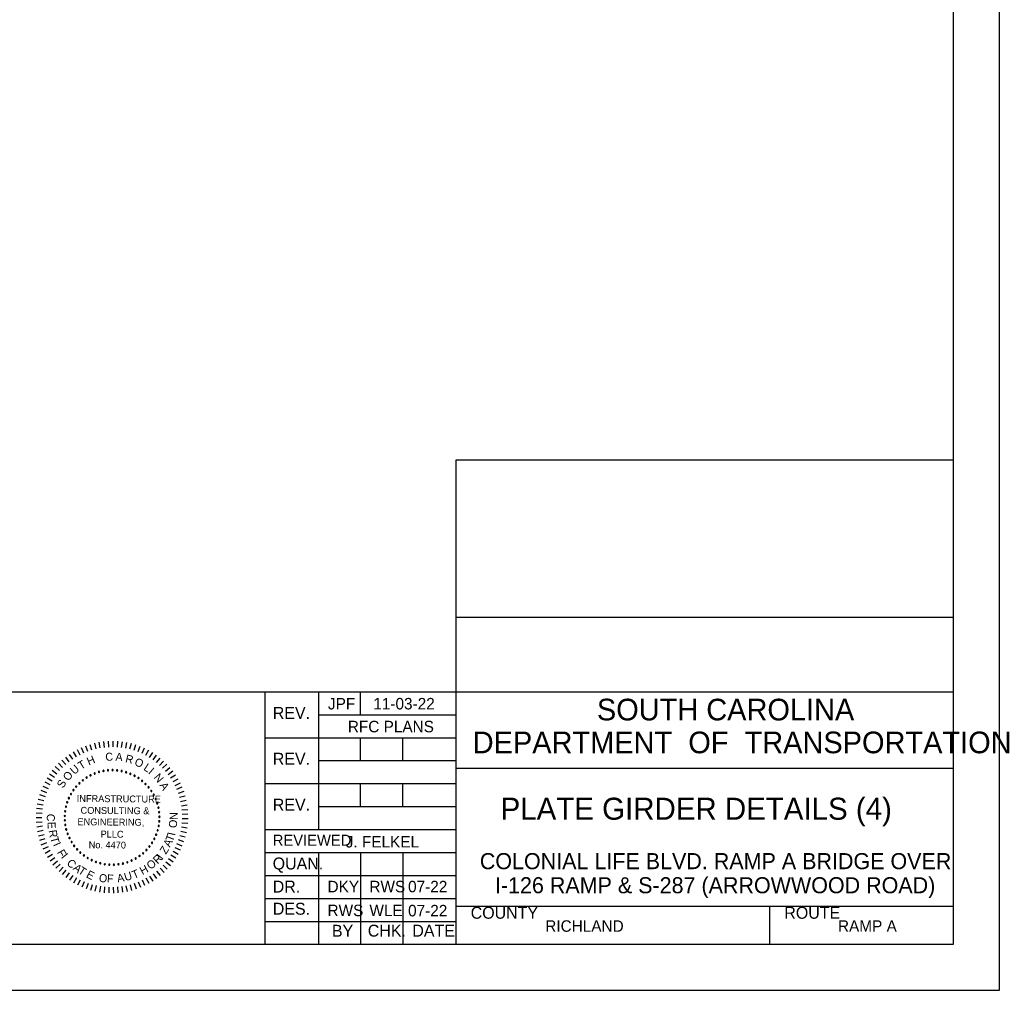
# Model space of a CAD drawing. Extents: x -383 to 11, y -361 to -94.
# Drawn here: x -203.87 to -160.75, y -187.49 to -145.21 of the extents above; entities that cross this region are included whole.
import ezdxf

# ---------------------------------------------------------------- set-up
doc = ezdxf.new("R2010")
doc.units = 0
for name, color, linetype in [('BR_BORDER LINES', 7, 'Continuous'), ('BR_TEXT', 7, 'Continuous'), ('Level 31', 7, 'Continuous')]:
    doc.layers.add(name, color=color, linetype=linetype)

msp = doc.modelspace()

# ---------------------------------------------------------------- linework, layer by layer
at = {"layer": 'BR_BORDER LINES'}
for p, q in [((-163.178, -185.489), (-163.178, -101.489)), ((-184.846, -185.489), (-184.846, -164.383)), ((-184.846, -164.383), (-163.178, -164.383)), ((-184.845, -171.242), (-163.178, -171.242)), ((-214.64, -174.489), (-193.18, -174.489)), ((-193.18, -185.489), (-193.18, -174.489)), ((-193.18, -174.489), (-163.178, -174.489)), ((-190.846, -174.489), (-190.846, -180.489)), ((-189.013, -175.489), (-189.013, -174.489)), ((-190.846, -175.489), (-184.846, -175.489)), ((-193.18, -176.489), (-184.846, -176.489)), ((-189.013, -177.489), (-189.013, -176.489)), ((-187.179, -177.489), (-187.179, -176.489)), ((-190.846, -177.489), (-184.846, -177.489)), ((-184.846, -177.822), (-184.846, -177.822)), ((-184.846, -177.823), (-163.178, -177.823)), ((-193.18, -178.489), (-184.846, -178.489)), ((-189.013, -179.489), (-189.013, -178.489)), ((-187.179, -179.489), (-187.179, -178.489)), ((-190.846, -179.489), (-184.846, -179.489)), ((-193.18, -180.489), (-184.846, -180.489)), ((-193.18, -181.489), (-184.846, -181.489)), ((-190.846, -181.489), (-190.846, -185.489)), ((-189.013, -181.489), (-189.013, -185.489)), ((-187.179, -181.489), (-187.179, -185.489)), ((-193.18, -182.489), (-184.846, -182.489)), ((-193.18, -183.489), (-184.846, -183.489)), ((-184.846, -183.823), (-163.178, -183.823)), ((-184.456, -183.823), (-163.178, -183.823)), ((-171.179, -185.489), (-171.179, -183.823)), ((-193.18, -184.489), (-184.846, -184.489)), ((-297.843, -185.489), (-163.178, -185.489))]:
    msp.add_line(p, q, dxfattribs=at)
at = {"layer": 'BR_TEXT'}
for p, q in [((-200.615, -176.726), (-200.555, -176.974)), ((-200.417, -176.685), (-200.373, -176.936)), ((-200.217, -176.656), (-200.188, -176.909)), ((-200.016, -176.64), (-200.002, -176.894)), ((-199.814, -176.636), (-199.816, -176.89)), ((-199.612, -176.644), (-199.63, -176.898)), ((-199.411, -176.664), (-199.444, -176.917)), ((-199.212, -176.697), (-199.26, -176.947)), ((-199.015, -176.741), (-199.079, -176.988)), ((-201.546, -177.106), (-201.415, -177.324)), ((-201.37, -177.007), (-201.252, -177.233)), ((-201.188, -176.92), (-201.084, -177.153)), ((-201.001, -176.844), (-200.912, -177.082)), ((-200.81, -176.779), (-200.735, -177.023)), ((-198.821, -176.798), (-198.9, -177.04)), ((-198.631, -176.866), (-198.724, -177.103)), ((-198.446, -176.946), (-198.553, -177.177)), ((-198.265, -177.037), (-198.387, -177.261)), ((-198.091, -177.139), (-198.226, -177.355)), ((-202.182, -177.601), (-202.002, -177.781)), ((-202.035, -177.463), (-201.866, -177.654)), ((-201.879, -177.334), (-201.723, -177.535)), ((-201.716, -177.215), (-201.572, -177.425)), ((-197.923, -177.251), (-198.071, -177.458)), ((-197.762, -177.373), (-197.922, -177.571)), ((-197.609, -177.505), (-197.781, -177.693)), ((-202.57, -178.065), (-202.36, -178.21)), ((-202.45, -177.903), (-202.25, -178.06)), ((-202.321, -177.748), (-202.13, -177.917)), ((-197.464, -177.646), (-197.647, -177.823)), ((-197.329, -177.795), (-197.522, -177.961)), ((-197.202, -177.952), (-197.405, -178.106)), ((-202.779, -178.411), (-202.553, -178.529)), ((-202.679, -178.235), (-202.461, -178.366)), ((-197.086, -178.117), (-197.298, -178.258)), ((-196.979, -178.289), (-197.199, -178.417)), ((-196.883, -178.467), (-197.111, -178.581)), ((-202.944, -178.779), (-202.705, -178.869)), ((-202.867, -178.593), (-202.634, -178.696)), ((-196.799, -178.65), (-197.033, -178.75)), ((-196.725, -178.838), (-196.965, -178.924)), ((-203.104, -179.363), (-202.853, -179.407)), ((-203.063, -179.165), (-202.815, -179.225)), ((-203.009, -178.97), (-202.766, -179.045)), ((-196.664, -179.03), (-196.908, -179.101)), ((-196.614, -179.226), (-196.862, -179.282)), ((-203.151, -179.764), (-202.897, -179.777)), ((-203.134, -179.562), (-202.881, -179.592)), ((-196.576, -179.424), (-196.827, -179.465)), ((-196.55, -179.625), (-196.804, -179.65)), ((-203.156, -179.965), (-202.901, -179.964)), ((-203.149, -180.167), (-202.895, -180.15)), ((-196.547, -180.23), (-196.8, -180.208)), ((-196.537, -179.826), (-196.791, -179.836)), ((-196.535, -180.028), (-196.79, -180.022)), ((-203.129, -180.368), (-202.877, -180.335)), ((-203.097, -180.568), (-202.847, -180.52)), ((-196.606, -180.629), (-196.855, -180.577)), ((-196.57, -180.43), (-196.822, -180.393)), ((-203.053, -180.765), (-202.807, -180.701)), ((-202.997, -180.959), (-202.755, -180.881)), ((-202.93, -181.149), (-202.693, -181.056)), ((-196.713, -181.018), (-196.954, -180.936)), ((-196.653, -180.825), (-196.899, -180.758)), ((-202.851, -181.335), (-202.62, -181.228)), ((-202.761, -181.516), (-202.536, -181.395)), ((-196.96, -181.57), (-197.182, -181.446)), ((-196.867, -181.392), (-197.096, -181.281)), ((-196.784, -181.207), (-197.02, -181.111)), ((-202.66, -181.69), (-202.443, -181.556)), ((-202.548, -181.859), (-202.34, -181.711)), ((-202.426, -182.02), (-202.228, -181.86)), ((-197.304, -182.068), (-197.5, -181.905)), ((-197.179, -181.91), (-197.385, -181.759)), ((-197.065, -181.743), (-197.279, -181.605)), ((-202.295, -182.173), (-202.107, -182.002)), ((-202.155, -182.319), (-201.977, -182.136)), ((-202.006, -182.455), (-201.84, -182.262)), ((-201.849, -182.582), (-201.695, -182.379)), ((-197.733, -182.495), (-197.895, -182.3)), ((-197.581, -182.362), (-197.756, -182.176)), ((-197.438, -182.219), (-197.623, -182.045)), ((-201.685, -182.699), (-201.543, -182.487)), ((-201.513, -182.806), (-201.385, -182.586)), ((-201.336, -182.903), (-201.221, -182.675)), ((-201.153, -182.988), (-201.053, -182.754)), ((-198.596, -183.012), (-198.692, -182.777)), ((-198.411, -182.93), (-198.522, -182.701)), ((-198.232, -182.837), (-198.356, -182.615)), ((-198.059, -182.734), (-198.196, -182.519)), ((-197.892, -182.62), (-198.042, -182.414)), ((-200.965, -183.062), (-200.879, -182.822)), ((-200.773, -183.125), (-200.702, -182.88)), ((-200.577, -183.175), (-200.521, -182.927)), ((-200.379, -183.214), (-200.338, -182.962)), ((-200.179, -183.24), (-200.154, -182.987)), ((-199.978, -183.254), (-199.968, -183)), ((-199.776, -183.256), (-199.781, -183.002)), ((-199.574, -183.246), (-199.595, -182.992)), ((-199.373, -183.223), (-199.41, -182.971)), ((-199.174, -183.188), (-199.226, -182.939)), ((-198.978, -183.142), (-199.045, -182.896)), ((-198.785, -183.083), (-198.867, -182.842))]:
    msp.add_line(p, q, dxfattribs=at)
for centre, start, end in [((-200.603, -178.045), 21.6807, 201.6807), ((-200.603, -178.045), 201.6807, 21.6807), ((-200.414, -177.98), 16.1422, 196.1422), ((-200.414, -177.98), 196.1422, 16.1422), ((-200.22, -177.935), 10.6038, 190.6038), ((-200.22, -177.935), 190.6038, 10.6038), ((-200.023, -177.908), 5.0653, 185.0653), ((-200.023, -177.908), 185.0653, 5.0653), ((-199.824, -177.9), 359.5268, 179.5268), ((-199.824, -177.9), 179.5268, 359.5268), ((-199.625, -177.912), 353.9884, 173.9884), ((-199.625, -177.912), 173.9884, 353.9884), ((-199.428, -177.943), 168.4499, 348.4499), ((-199.428, -177.943), 348.4499, 168.4499), ((-199.235, -177.992), 162.9114, 342.9114), ((-199.235, -177.992), 342.9114, 162.9114), ((-199.047, -178.06), 157.373, 337.373), ((-199.047, -178.06), 337.373, 157.373), ((-201.27, -178.472), 43.8345, 223.8345), ((-201.27, -178.472), 223.8345, 43.8345), ((-201.12, -178.341), 38.2961, 218.2961), ((-201.12, -178.341), 218.2961, 38.2961), ((-200.957, -178.226), 32.7576, 212.7576), ((-200.957, -178.226), 212.7576, 32.7576), ((-200.785, -178.127), 27.2191, 207.2191), ((-200.785, -178.127), 207.2191, 27.2191), ((-198.867, -178.146), 151.8345, 331.8345), ((-198.867, -178.146), 331.8345, 151.8345), ((-198.697, -178.249), 146.2961, 326.2961), ((-198.697, -178.249), 326.2961, 146.2961), ((-198.537, -178.368), 140.7576, 320.7576), ((-198.537, -178.368), 320.7576, 140.7576), ((-198.389, -178.502), 135.2191, 315.2191), ((-198.389, -178.502), 315.2191, 135.2191), ((-201.637, -178.942), 60.4499, 240.4499), ((-201.637, -178.942), 240.4499, 60.4499), ((-201.53, -178.774), 54.9114, 234.9114), ((-201.53, -178.774), 234.9114, 54.9114), ((-201.408, -178.617), 49.373, 229.373), ((-201.408, -178.617), 229.373, 49.373), ((-198.255, -178.649), 129.6807, 309.6807), ((-198.255, -178.649), 309.6807, 129.6807), ((-198.135, -178.809), 124.1422, 304.1422), ((-198.135, -178.809), 304.1422, 124.1422), ((-201.8, -179.305), 71.5268, 251.5268), ((-201.8, -179.305), 251.5268, 71.5268), ((-201.727, -179.12), 65.9884, 245.9884), ((-201.727, -179.12), 245.9884, 65.9884), ((-198.032, -178.979), 118.6038, 298.6038), ((-198.032, -178.979), 298.6038, 118.6038), ((-197.945, -179.159), 113.0653, 293.0653), ((-197.945, -179.159), 293.0653, 113.0653), ((-197.876, -179.346), 107.5268, 287.5268), ((-197.876, -179.346), 287.5268, 107.5268), ((-201.89, -179.693), 82.6038, 262.6038), ((-201.89, -179.693), 262.6038, 82.6038), ((-201.854, -179.497), 77.0653, 257.0653), ((-201.854, -179.497), 257.0653, 77.0653), ((-197.826, -179.538), 101.9884, 281.9884), ((-197.826, -179.538), 281.9884, 101.9884), ((-197.795, -179.735), 96.4499, 276.4499), ((-197.795, -179.735), 276.4499, 96.4499), ((-201.906, -179.892), 88.1422, 268.1422), ((-201.904, -180.091), 93.6807, 273.6807), ((-201.906, -179.892), 268.1422, 88.1422), ((-201.904, -180.091), 273.6807, 93.6807), ((-197.789, -180.133), 85.373, 265.373), ((-197.782, -179.934), 90.9114, 270.9114), ((-197.789, -180.133), 265.373, 85.373), ((-197.782, -179.934), 270.9114, 90.9114), ((-201.882, -180.289), 99.2191, 279.2191), ((-201.882, -180.289), 279.2191, 99.2191), ((-201.841, -180.484), 104.7576, 284.7576), ((-201.841, -180.484), 284.7576, 104.7576), ((-201.781, -180.675), 110.2961, 290.2961), ((-201.781, -180.675), 290.2961, 110.2961), ((-197.86, -180.525), 74.2961, 254.2961), ((-197.86, -180.525), 254.2961, 74.2961), ((-197.815, -180.331), 79.8345, 259.8345), ((-197.815, -180.331), 259.8345, 79.8345), ((-201.703, -180.858), 115.8345, 295.8345), ((-201.703, -180.858), 295.8345, 115.8345), ((-201.608, -181.033), 121.373, 301.373), ((-201.608, -181.033), 301.373, 121.373), ((-198.104, -181.069), 57.6807, 237.6807), ((-198.104, -181.069), 237.6807, 57.6807), ((-198.005, -180.896), 63.2191, 243.2191), ((-198.005, -180.896), 243.2191, 63.2191), ((-197.924, -180.714), 68.7576, 248.7576), ((-197.924, -180.714), 248.7576, 68.7576), ((-201.497, -181.199), 126.9114, 306.9114), ((-201.497, -181.199), 306.9114, 126.9114), ((-201.37, -181.352), 132.4499, 312.4499), ((-201.37, -181.352), 312.4499, 132.4499), ((-201.228, -181.493), 137.9884, 317.9884), ((-201.228, -181.493), 317.9884, 137.9884), ((-198.493, -181.521), 41.0653, 221.0653), ((-198.493, -181.521), 221.0653, 41.0653), ((-198.349, -181.383), 46.6038, 226.6038), ((-198.349, -181.383), 226.6038, 46.6038), ((-198.219, -181.232), 52.1422, 232.1422), ((-198.219, -181.232), 232.1422, 52.1422), ((-201.074, -181.619), 143.5268, 323.5268), ((-201.074, -181.619), 323.5268, 143.5268), ((-200.909, -181.73), 149.0653, 329.0653), ((-200.909, -181.73), 329.0653, 149.0653), ((-200.733, -181.825), 154.6038, 334.6038), ((-200.733, -181.825), 334.6038, 154.6038), ((-200.549, -181.902), 160.1422, 340.1422), ((-200.549, -181.902), 340.1422, 160.1422), ((-200.359, -181.961), 345.6807, 165.6807), ((-199.372, -181.971), 13.373, 193.373), ((-199.18, -181.916), 18.9114, 198.9114), ((-199.18, -181.916), 198.9114, 18.9114), ((-198.995, -181.842), 24.4499, 204.4499), ((-198.995, -181.842), 204.4499, 24.4499), ((-198.817, -181.752), 29.9884, 209.9884), ((-198.817, -181.752), 209.9884, 29.9884), ((-198.649, -181.644), 35.5268, 215.5268), ((-198.649, -181.644), 215.5268, 35.5268), ((-200.359, -181.961), 165.6807, 345.6807), ((-200.164, -182.001), 171.2191, 351.2191), ((-200.164, -182.001), 351.2191, 171.2191), ((-199.965, -182.022), 176.7576, 356.7576), ((-199.965, -182.022), 356.7576, 176.7576), ((-199.766, -182.024), 2.2961, 182.2961), ((-199.766, -182.024), 182.2961, 2.2961), ((-199.568, -182.007), 7.8345, 187.8345), ((-199.568, -182.007), 187.8345, 7.8345), ((-199.372, -181.971), 193.373, 13.373)]:
    msp.add_arc(centre, 0.028, start, end, dxfattribs=at)
at = {"layer": 'Level 31'}
msp.add_line((-174.011, -179.583), (-174.011, -179.583), dxfattribs=at)
msp.add_lwpolyline([(-305.176, -187.489), (-161.176, -187.489), (-161.176, -99.489), (-305.176, -99.489)], close=True, dxfattribs=at)

# ---------------------------------------------------------------- texts
at = {"layer": 'BR_TEXT'}
for s, height, p in [('JPF', 0.5, (-190.438, -175.257)), ('11-03-22', 0.5, (-188.461, -175.257)), ('SOUTH CAROLINA', 0.94348, (-178.718, -175.735)), ('REV.', 0.52, (-192.841, -175.667)), ('RFC PLANS', 0.5, (-189.572, -176.253)), ('DEPARTMENT  OF  TRANSPORTATION', 0.94348, (-184.129, -177.166)), ('REV.', 0.52, (-192.841, -177.667)), ('REV.', 0.52, (-192.841, -179.667)), ('PLATE GIRDER DETAILS (4)', 0.96, (-182.913, -180.063)), ('REVIEWED', 0.48, (-192.843, -181.195)), ('J. FELKEL', 0.5, (-189.664, -181.272)), ('COLONIAL LIFE BLVD. RAMP A BRIDGE OVER', 0.7, (-183.82, -182.216)), ('QUAN.', 0.52, (-192.846, -182.229)), ('DR.', 0.52, (-192.845, -183.235)), ('DKY', 0.5, (-190.457, -183.224)), ('RWS', 0.5, (-188.632, -183.224)), ('07-22', 0.5, (-186.946, -183.224)), ('I-126 RAMP & S-287 (ARROWWOOD ROAD)', 0.7, (-183.162, -183.266)), ('DES.', 0.52, (-192.841, -184.2)), ('RWS', 0.5, (-190.457, -184.263)), ('WLE', 0.5, (-188.63, -184.263)), ('07-22', 0.5, (-186.946, -184.272)), ('COUNTY', 0.52, (-184.217, -184.376)), ('ROUTE', 0.52, (-170.55, -184.376)), ('RICHLAND', 0.5, (-180.968, -184.944)), ('RAMP A', 0.5, (-168.212, -184.944)), ('BY', 0.52, (-190.265, -185.161)), ('CHK.', 0.52, (-188.701, -185.156)), ('DATE', 0.52, (-186.761, -185.156))]:
    msp.add_text(s, height=height, dxfattribs=at).set_placement(p)
for s, height, rotation, p in [('C', 0.349, 4.7281, (-200.126, -177.506)), ('A', 0.349, 355.6981, (-199.708, -177.486)), ('T', 0.349, 31.8182, (-201.196, -177.894)), ('H', 0.349, 22.7882, (-200.857, -177.704)), ('R', 0.349, 346.6681, (-199.291, -177.554)), ('O', 0.349, 337.638, (-198.9, -177.673)), ('L', 0.349, 327.108, (-198.504, -177.875)), ('O', 0.349, 49.8782, (-201.757, -178.403)), ('U', 0.349, 40.8482, (-201.49, -178.119)), ('I', 0.349, 319.578, (-198.294, -178.026)), ('N', 0.349, 310.548, (-198.051, -178.23)), ('S', 0.349, 58.9083, (-201.979, -178.715)), ('A', 0.349, 301.5179, (-197.791, -178.559)), ('INFRASTRUCTURE', 0.29909, 359.5268, (-201.385, -179.286)), ('CONSULTING &', 0.29909, 359.5268, (-201.22, -179.8)), ('N', 0.349, 89.2085, (-196.993, -180.074)), ('C', 0.349, 267.025, (-202.679, -179.795)), ('E', 0.349, 273.025, (-202.662, -180.161)), ('ENGINEERING,', 0.29909, 359.5268, (-201.354, -180.302)), ('O', 0.349, 83.2085, (-197.038, -180.44)), ('R', 0.349, 279.025, (-202.61, -180.531)), ('PLLC', 0.2991, 359.5268, (-200.347, -180.836)), ('I', 0.349, 77.9093, (-197.1, -180.777)), ('T', 0.349, 285.025, (-202.541, -180.846)), ('I', 0.349, 293.7713, (-202.422, -181.138)), ('No. 4470', 0.2991, 359.5268, (-200.865, -181.304)), ('A', 0.349, 63.3954, (-197.326, -181.288)), ('T', 0.349, 69.3954, (-197.203, -181.047)), ('F', 0.349, 299.7713, (-202.257, -181.482)), ('I', 0.349, 308.5268, (-202.089, -181.698)), ('Z', 0.349, 57.3954, (-197.501, -181.594)), ('C', 0.349, 314.5268, (-201.851, -181.978)), ('O', 0.349, 38.5268, (-198.169, -182.254)), ('R', 0.349, 44.5268, (-197.863, -182.014)), ('I', 0.349, 52.3339, (-197.665, -181.825)), ('A', 0.349, 320.5268, (-201.575, -182.213)), ('T', 0.349, 326.5268, (-201.357, -182.366)), ('E', 0.349, 332.5268, (-201.003, -182.558)), ('U', 0.349, 16.5268, (-199.261, -182.742)), ('T', 0.349, 22.5268, (-198.894, -182.645)), ('H', 0.349, 28.5268, (-198.522, -182.478)), ('O', 0.349, 350.5268, (-200.442, -182.753)), ('F', 0.349, 356.5268, (-200.076, -182.79)), ('A', 0.349, 10.5268, (-199.597, -182.796))]:
    msp.add_text(s, height=height, rotation=rotation, dxfattribs=at).set_placement(p)

doc.saveas('drawing.dxf')
